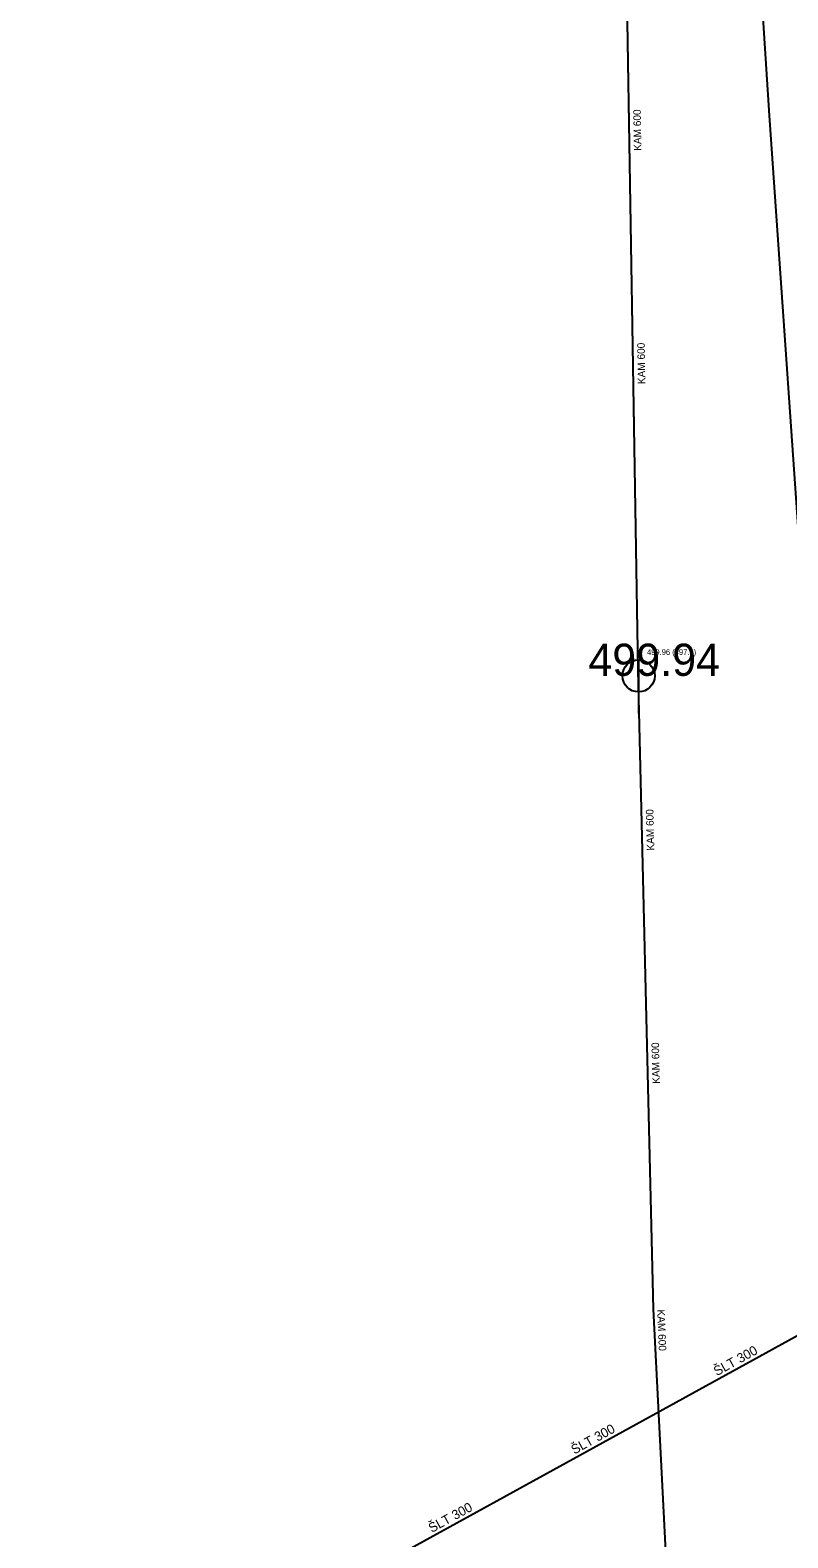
# Model space of a CAD drawing. Extents: x -668867 to -667827, y -1131943 to -1131019.
# Drawn here: x -668268.62 to -668250.96, y -1131446.96 to -1131411.84 of the extents above; entities that cross this region are included whole.
import ezdxf

# ---------------------------------------------------------------- set-up
doc = ezdxf.new("R2010")
doc.units = 0
for name, color, linetype in [('G_Bod_tecka', 7, 'Continuous'), ('G_Bod_vyska', 7, 'Continuous'), ('G_Breh_Teren', 7, 'Continuous'), ('G_Site-kanalizace', 7, 'Continuous'), ('G_Z_KANAL_podz_kotovane', 7, 'Continuous'), ('G_Z_VODA_podz_kotovane', 7, 'Continuous'), ('Vrstva 12', 7, 'Continuous'), ('Vrstva 2', 7, 'Continuous'), ('Vrstva 25', 7, 'Continuous'), ('Vrstva 3', 7, 'Continuous'), ('Vrstva 4', 7, 'Continuous'), ('Vrstva 8', 7, 'Continuous')]:
    doc.layers.add(name, color=color, linetype=linetype)

msp = doc.modelspace()

# ---------------------------------------------------------------- linework, layer by layer
at = {"layer": 'G_Bod_tecka'}
msp.add_line((-668254.44, -1131426.88), (-668254.44, -1131426.88), dxfattribs=at)
at = {"layer": 'G_Breh_Teren'}
msp.add_lwpolyline([(-668247.21, -1131459.56), (-668247.36, -1131457.58), (-668247.5, -1131455.61), (-668247.72, -1131452.96), (-668248.22, -1131448.32), (-668249.07, -1131441.38), (-668249.48, -1131437.9), (-668249.84, -1131434.42), (-668250.53, -1131426.19), (-668251.39, -1131413.83), (-668252.19, -1131401.47)], dxfattribs=at)
at = {"layer": 'G_Site-kanalizace'}
msp.add_line((-668254.44, -1131426.505), (-668254.44, -1131427.755), dxfattribs=at)
msp.add_circle((-668254.44, -1131426.88), 0.375, dxfattribs=at)
at = {"layer": 'G_Z_KANAL_podz_kotovane'}
for points in [[(-668254.45, -1131426.75), (-668254.73, -1131409.75), (-668254.88, -1131387.95)], [(-668253.3, -1131457.19), (-668254.09, -1131441.63), (-668254.45, -1131426.75)]]:
    msp.add_lwpolyline(points, dxfattribs=at)
at = {"layer": 'G_Z_VODA_podz_kotovane'}
msp.add_line((-668301.2, -1131469.98), (-668198.9, -1131413.75), dxfattribs=at)
at = {"layer": 'Vrstva 12'}
for points in [[(-668254.449, -1131426.745), (-668254.73, -1131409.747), (-668254.877, -1131387.947)], [(-668253.3, -1131457.19), (-668254.092, -1131441.634), (-668254.449, -1131426.745)]]:
    msp.add_lwpolyline(points, dxfattribs=at)
at = {"layer": 'Vrstva 25'}
msp.add_line((-668301.2, -1131469.98), (-668198.898, -1131413.745), dxfattribs=at)
at = {"layer": 'Vrstva 8'}
msp.add_line((-668254.449, -1131426.745), (-668254.449, -1131426.745), dxfattribs=at)

# ---------------------------------------------------------------- texts
at = {"layer": 'G_Bod_vyska'}
msp.add_text('499.94', height=0.75, dxfattribs=at).set_placement((-668255.61, -1131426.88))
at = {"layer": 'Vrstva 2'}
msp.add_text('499.96 (497.1)', height=0.13163, dxfattribs=at).set_placement((-668254.244, -1131426.392))
at = {"layer": 'Vrstva 3'}
for rotation, p in [(90.9329, (-668254.374, -1131414.65)), (90.9329, (-668254.282, -1131420.084)), (91.3838, (-668254.073, -1131430.948)), (91.3838, (-668253.943, -1131436.381)), (272.2861, (-668254.007, -1131441.642))]:
    msp.add_text('KAM 600', height=0.1755, rotation=rotation, dxfattribs=at).set_placement(p)
at = {"layer": 'Vrstva 4'}
for rotation, p in [(28.797, (-668252.617, -1131443.193)), (28.7844, (-668255.938, -1131445.019)), (28.758, (-668259.26, -1131446.845))]:
    msp.add_text('ŠLT 300', height=0.2194, rotation=rotation, dxfattribs=at).set_placement(p)

doc.saveas('drawing.dxf')
